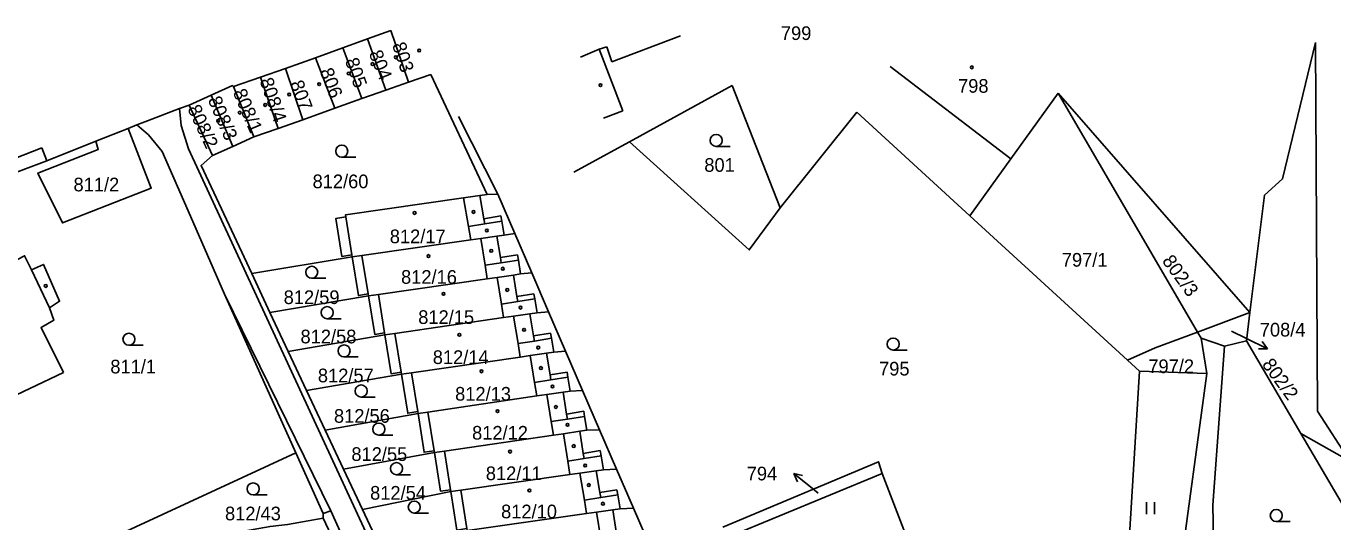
# Model space of a CAD drawing. Extents: x -776701 to -776081, y -974398 to -973771.
# Drawn here: x -776392 to -776229.3, y -973832.8 to -973771.1 of the extents above; entities that cross this region are included whole.
import ezdxf

# ---------------------------------------------------------------- set-up
doc = ezdxf.new("R2010")
doc.units = 0
for name, color, linetype in [('Hranice parcel', 7, 'Continuous'), ('Parcelní čísla', 7, 'Continuous'), ('Pop  PČ popisy', 7, 'Continuous'), ('Vnitřní kresba', 7, 'Continuous'), ('Značky budov', 7, 'Continuous'), ('Značky kultur', 7, 'Continuous')]:
    doc.layers.add(name, color=color, linetype=linetype)

msp = doc.modelspace()

# ---------------------------------------------------------------- linework, layer by layer
at = {"layer": 'Hranice parcel'}
for p, q in [((-776349.48, -973772.73), (-776352.55, -973773.84)), ((-776346.57, -973771.67), (-776349.48, -973772.73)), ((-776349.48, -973772.73), (-776347.21, -973779.11)), ((-776346.57, -973771.67), (-776344.4, -973778.13)), ((-776352.55, -973773.84), (-776355.96, -973775.07)), ((-776352.55, -973773.84), (-776350.2, -973780.16)), ((-776231.52, -973773.2), (-776231.27, -973819.06)), ((-776355.96, -973775.07), (-776359.71, -973776.43)), ((-776355.96, -973775.07), (-776353.54, -973781.33)), ((-776362.79, -973777.49), (-776366.18, -973778.65)), ((-776359.71, -973776.43), (-776362.79, -973777.49)), ((-776360.61, -973783.88), (-776362.79, -973777.49)), ((-776359.71, -973776.43), (-776357.53, -973782.82)), ((-776344.4, -973778.13), (-776341.61, -973777.15)), ((-776334.61, -973792.1), (-776341.61, -973777.15)), ((-776366.18, -973778.65), (-776363.61, -973784.92)), ((-776350.2, -973780.16), (-776347.21, -973779.11)), ((-776347.21, -973779.11), (-776344.4, -973778.13)), ((-776316.87, -973785.52), (-776304.09, -973778.55)), ((-776304.09, -973778.55), (-776298.13, -973793.76)), ((-776246.18, -973809.21), (-776263.55, -973779.48)), ((-776263.55, -973779.48), (-776239.66, -973806.76)), ((-776371.66, -973780.97), (-776372.87, -973781.39)), ((-776368.93, -973779.73), (-776371.66, -973780.97)), ((-776371.66, -973780.97), (-776368.77, -973787.24)), ((-776366.25, -973786.11), (-776368.93, -973779.73)), ((-776353.54, -973781.33), (-776350.2, -973780.16)), ((-776360.61, -973783.88), (-776357.53, -973782.82)), ((-776357.53, -973782.82), (-776353.54, -973781.33)), ((-776288.6, -973781.83), (-776298.13, -973793.76)), ((-776274.51, -973794.74), (-776288.6, -973781.83)), ((-776379.29, -973783.88), (-776383.3, -973785.47)), ((-776378.19, -973783.44), (-776379.29, -973783.88)), ((-776363.61, -973784.92), (-776360.61, -973783.88)), ((-776366.25, -973786.11), (-776363.61, -973784.92)), ((-776368.77, -973787.24), (-776366.25, -973786.11)), ((-776237.86, -973792.19), (-776239.66, -973806.76)), ((-776254.9, -973812.71), (-776274.51, -973794.74)), ((-776329.05, -973801.83), (-776331.17, -973796.94)), ((-776351.39, -973799.85), (-776363.9, -973801.91)), ((-776361.62, -973806.76), (-776363.9, -973801.91)), ((-776326.94, -973806.71), (-776329.05, -973801.83)), ((-776349.35, -973804.71), (-776361.62, -973806.76)), ((-776359.35, -973811.61), (-776361.62, -973806.76)), ((-776324.83, -973811.6), (-776326.94, -973806.71)), ((-776239.66, -973806.76), (-776246.18, -973809.21)), ((-776239.66, -973806.76), (-776240.1, -973810.31)), ((-776347.32, -973809.55), (-776359.35, -973811.61)), ((-776245.75, -973809.95), (-776246.18, -973809.21)), ((-776242.84, -973810.95), (-776245.75, -973809.95)), ((-776245.75, -973809.95), (-776245.02, -973814.37)), ((-776240.1, -973810.31), (-776242.84, -973810.95)), ((-776233.34, -973821.83), (-776240.1, -973810.31)), ((-776357.07, -973816.46), (-776359.35, -973811.61)), ((-776322.72, -973816.48), (-776324.83, -973811.6)), ((-776253.42, -973814.06), (-776254.9, -973812.71)), ((-776345.26, -973814.46), (-776357.07, -973816.46)), ((-776255.89, -973854.42), (-776253.42, -973814.06)), ((-776245.02, -973814.37), (-776253.42, -973814.06)), ((-776354.75, -973821.4), (-776357.07, -973816.46)), ((-776320.6, -973821.36), (-776322.72, -973816.48)), ((-776343.2, -973819.35), (-776354.75, -973821.4)), ((-776352.47, -973826.25), (-776354.75, -973821.4)), ((-776318.49, -973826.25), (-776320.6, -973821.36)), ((-776220.95, -973842.92), (-776233.34, -973821.83)), ((-776358.4, -973824.22), (-776389.33, -973838.52)), ((-776341.16, -973824.21), (-776352.47, -973826.25)), ((-776350.11, -973831.28), (-776352.47, -973826.25)), ((-776316.38, -973831.13), (-776318.49, -973826.25)), ((-776285.43, -973826.82), (-776304.74, -973834.76)), ((-776278.45, -973844.96), (-776285.43, -973826.82)), ((-776339.12, -973829.06), (-776350.11, -973831.28)), ((-776347.94, -973835.9), (-776350.11, -973831.28)), ((-776314.27, -973836.02), (-776316.38, -973831.13)), ((-776352.67, -973837.34), (-776354.99, -973832.34))]:
    msp.add_line(p, q, dxfattribs=at)
for points in [[(-776237.86, -973792.19), (-776235.61, -973790.15), (-776231.52, -973773.2)], [(-776366.18, -973778.65), (-776366.29, -973778.54), (-776368.93, -973779.73)], [(-776274.51, -973794.74), (-776269.43, -973787.66), (-776263.55, -973779.48)], [(-776372.87, -973781.39), (-776376.87, -973782.92), (-776378.19, -973783.44)], [(-776372.87, -973781.39), (-776372.69, -973783.49), (-776371.76, -973786.4), (-776344.07, -973846.28), (-776320.78, -973896.42)], [(-776379.29, -973783.88), (-776376.4, -973791.29), (-776387.45, -973795.62), (-776390.5, -973789.42), (-776383, -973786.49), (-776383.3, -973785.47)], [(-776378.19, -973783.44), (-776376.74, -973784.67), (-776375.05, -973786.75), (-776371.5, -973794.8), (-776367.29, -973804.51), (-776358.4, -973824.22)], [(-776383.3, -973785.47), (-776389.4, -973787.9), (-776406.97, -973794.51)], [(-776298.13, -973793.76), (-776301.98, -973798.98), (-776316.87, -973785.52)], [(-776363.9, -973801.91), (-776370.19, -973788.49), (-776368.77, -973787.24)], [(-776334.61, -973792.1), (-776335.5, -973792.23), (-776337.53, -973792.52), (-776352.21, -973794.62), (-776352.17, -973794.87), (-776353.42, -973795.06), (-776352.68, -973799.8), (-776351.43, -973799.6), (-776351.39, -973799.85)], [(-776331.17, -973796.94), (-776333.28, -973792.06), (-776334.61, -973792.1)], [(-776387.3, -973814.25), (-776390.1, -973808.63), (-776388.5, -973807.73), (-776389.05, -973806.2), (-776387.8, -973805.38), (-776389.82, -973800.79), (-776391.31, -973801.47), (-776392.16, -973799.72), (-776393.84, -973800.61), (-776396.57, -973794.81), (-776405.01, -973798.86), (-776395.74, -973818.2), (-776387.3, -973814.25)], [(-776331.17, -973796.94), (-776332.48, -973797.15), (-776333.37, -973797.28), (-776335.4, -973797.57), (-776336.64, -973797.75), (-776350.2, -973799.68), (-776351.39, -973799.85)], [(-776351.39, -973799.85), (-776350.62, -973804.66), (-776349.39, -973804.46), (-776349.35, -973804.71)], [(-776329.05, -973801.83), (-776330.43, -973801.98), (-776331.32, -973802.11), (-776333.35, -973802.4), (-776334.59, -973802.58), (-776348.11, -973804.53), (-776349.35, -973804.71)], [(-776349.35, -973804.71), (-776348.59, -973809.5), (-776347.36, -973809.3), (-776347.32, -973809.55)], [(-776326.94, -973806.71), (-776328.39, -973806.81), (-776329.28, -973806.94), (-776331.31, -973807.23), (-776332.55, -973807.41), (-776346.08, -973809.37), (-776347.32, -973809.55)], [(-776347.32, -973809.55), (-776346.53, -973814.41), (-776345.3, -973814.21), (-776345.26, -973814.46)], [(-776254.9, -973812.71), (-776251.48, -973811.15), (-776246.18, -973809.21)], [(-776324.83, -973811.6), (-776326.31, -973811.71), (-776327.2, -973811.84), (-776329.23, -973812.13), (-776330.47, -973812.31), (-776344.02, -973814.28), (-776345.26, -973814.46)], [(-776242.84, -973810.95), (-776244.28, -973830.76), (-776244.11, -973839.24), (-776247.09, -973857.16), (-776245.46, -973861.6)], [(-776345.26, -973814.46), (-776344.48, -973819.31), (-776343.24, -973819.11), (-776343.2, -973819.35)], [(-776245.02, -973814.37), (-776248.48, -973839.74), (-776251.52, -973854.49), (-776250.03, -973856.15)], [(-776322.72, -973816.48), (-776324.26, -973816.55), (-776325.15, -973816.68), (-776327.18, -973816.98), (-776328.42, -973817.16), (-776341.96, -973819.17), (-776343.2, -973819.35)], [(-776343.2, -973819.35), (-776342.44, -973824.16), (-776341.2, -973823.97), (-776341.16, -973824.21)], [(-776231.27, -973819.06), (-776227.23, -973825.26), (-776233.34, -973821.83)], [(-776320.6, -973821.36), (-776322.19, -973821.42), (-776323.08, -973821.55), (-776325.11, -973821.85), (-776326.35, -973822.03), (-776339.92, -973824.03), (-776341.16, -973824.21)], [(-776354.99, -973832.34), (-776354.99, -973831.79), (-776358.4, -973824.22)], [(-776341.16, -973824.21), (-776340.4, -973829.01), (-776339.16, -973828.82), (-776339.12, -973829.06)], [(-776318.49, -973826.25), (-776320.13, -973826.33), (-776321.02, -973826.46), (-776323.05, -973826.75), (-776324.29, -973826.93), (-776337.88, -973828.88), (-776339.12, -973829.06)], [(-776285.43, -973826.82), (-776285.89, -973825.34), (-776305.26, -973833.49)], [(-776339.12, -973829.06), (-776338.37, -973833.84), (-776337.14, -973833.65), (-776337.1, -973833.89)], [(-776316.38, -973831.13), (-776318.06, -973831.21), (-776318.95, -973831.33), (-776320.98, -973831.62), (-776322.22, -973831.79), (-776335.86, -973833.72), (-776337.1, -973833.89)], [(-776354.99, -973832.34), (-776359.44, -973833.16), (-776361.61, -973833.38), (-776376.11, -973835.95), (-776375.11, -973841.2)]]:
    msp.add_lwpolyline(points, dxfattribs=at)
at = {"layer": 'Pop  PČ popisy'}
for p, q in [((-776241.96, -973809.1), (-776240.17, -973809.97)), ((-776240.17, -973809.97), (-776237.47, -973811.29)), ((-776237.47, -973811.29), (-776238.15, -973810.4)), ((-776237.47, -973811.29), (-776238.59, -973811.3)), ((-776294.11, -973828.69), (-776296.44, -973826.8)), ((-776296.44, -973826.8), (-776295.35, -973827.04)), ((-776296.44, -973826.8), (-776295.98, -973827.82)), ((-776293.39, -973829.27), (-776294.11, -973828.69))]:
    msp.add_line(p, q, dxfattribs=at)
at = {"layer": 'Vnitřní kresba'}
for p, q in [((-776310.53, -973772.37), (-776319.09, -973775.6)), ((-776320.64, -973774), (-776322.96, -973775)), ((-776319.7, -973773.7), (-776320.64, -973774)), ((-776320.64, -973774), (-776317.69, -973781.7)), ((-776319.09, -973775.6), (-776319.7, -973773.7)), ((-776269.43, -973787.66), (-776284.44, -973776.16)), ((-776333.28, -973792.06), (-776338.14, -973782.38)), ((-776317.69, -973781.7), (-776320.11, -973782.59)), ((-776316.87, -973785.52), (-776323.79, -973789.3)), ((-776390.01, -973786.27), (-776408.2, -973793.39)), ((-776389.4, -973787.9), (-776390.01, -973786.27)), ((-776337.53, -973792.52), (-776336.92, -973796.08)), ((-776335.01, -973795.11), (-776335.5, -973792.23)), ((-776351.43, -973799.6), (-776352.17, -973794.87)), ((-776336.92, -973796.08), (-776334.9, -973795.75)), ((-776332.89, -973794.75), (-776335.01, -973795.11)), ((-776335.01, -973795.11), (-776334.9, -973795.75)), ((-776334.9, -973795.75), (-776332.78, -973795.39)), ((-776332.78, -973795.39), (-776332.89, -973794.75)), ((-776332.78, -973795.39), (-776332.48, -973797.15)), ((-776336.92, -973796.08), (-776336.64, -973797.75)), ((-776332.94, -973799.95), (-776333.37, -973797.28)), ((-776335.4, -973797.57), (-776334.86, -973800.9)), ((-776350.2, -973799.68), (-776349.39, -973804.46)), ((-776334.86, -973800.9), (-776332.83, -973800.59)), ((-776332.94, -973799.95), (-776330.81, -973799.61)), ((-776332.83, -973800.59), (-776332.94, -973799.95)), ((-776330.71, -973800.25), (-776332.83, -973800.59)), ((-776330.81, -973799.61), (-776330.71, -973800.25)), ((-776330.71, -973800.25), (-776330.43, -973801.98)), ((-776389.05, -973806.2), (-776391.31, -973801.47)), ((-776334.86, -973800.9), (-776334.59, -973802.58)), ((-776331.32, -973802.11), (-776330.89, -973804.78)), ((-776332.82, -973805.73), (-776333.35, -973802.4)), ((-776367.29, -973804.51), (-776354.06, -973831.46)), ((-776348.11, -973804.53), (-776347.36, -973809.3)), ((-776330.79, -973805.42), (-776332.82, -973805.73)), ((-776328.77, -973804.44), (-776330.89, -973804.78)), ((-776330.89, -973804.78), (-776330.79, -973805.42)), ((-776330.79, -973805.42), (-776328.66, -973805.08)), ((-776328.66, -973805.08), (-776328.77, -973804.44)), ((-776328.39, -973806.81), (-776328.66, -973805.08)), ((-776332.55, -973807.41), (-776332.82, -973805.73)), ((-776329.28, -973806.94), (-776328.83, -973809.68)), ((-776330.75, -973810.63), (-776331.31, -973807.23)), ((-776346.08, -973809.37), (-776345.3, -973814.21)), ((-776328.72, -973810.32), (-776330.75, -973810.63)), ((-776326.71, -973809.33), (-776328.83, -973809.68)), ((-776328.83, -973809.68), (-776328.72, -973810.32)), ((-776328.72, -973810.32), (-776326.6, -973809.97)), ((-776326.6, -973809.97), (-776326.71, -973809.33)), ((-776326.31, -973811.71), (-776326.6, -973809.97)), ((-776330.47, -973812.31), (-776330.75, -973810.63)), ((-776327.2, -973811.84), (-776326.76, -973814.53)), ((-776328.69, -973815.48), (-776329.23, -973812.13)), ((-776344.02, -973814.28), (-776343.24, -973819.11)), ((-776326.66, -973815.17), (-776328.69, -973815.48)), ((-776324.64, -973814.19), (-776326.76, -973814.53)), ((-776326.76, -973814.53), (-776326.66, -973815.17)), ((-776326.66, -973815.17), (-776324.54, -973814.83)), ((-776324.54, -973814.83), (-776324.64, -973814.19)), ((-776324.26, -973816.55), (-776324.54, -973814.83)), ((-776328.42, -973817.16), (-776328.69, -973815.48)), ((-776326.63, -973820.35), (-776327.18, -973816.98)), ((-776325.15, -973816.68), (-776324.7, -973819.41)), ((-776341.96, -973819.17), (-776341.2, -973823.97)), ((-776324.6, -973820.05), (-776326.63, -973820.35)), ((-776324.7, -973819.41), (-776322.58, -973819.06)), ((-776324.6, -973820.05), (-776324.7, -973819.41)), ((-776322.48, -973819.7), (-776324.6, -973820.05)), ((-776322.58, -973819.06), (-776322.48, -973819.7)), ((-776322.19, -973821.42), (-776322.48, -973819.7)), ((-776326.35, -973822.03), (-776326.63, -973820.35)), ((-776324.56, -973825.25), (-776325.11, -973821.85)), ((-776322.64, -973824.3), (-776323.08, -973821.55)), ((-776339.92, -973824.03), (-776339.16, -973828.82)), ((-776322.53, -973824.94), (-776324.56, -973825.25)), ((-776320.51, -973823.95), (-776322.64, -973824.3)), ((-776322.64, -973824.3), (-776322.53, -973824.94)), ((-776322.53, -973824.94), (-776320.41, -973824.59)), ((-776320.41, -973824.59), (-776320.51, -973823.95)), ((-776320.13, -973826.33), (-776320.41, -973824.59)), ((-776324.29, -973826.93), (-776324.56, -973825.25)), ((-776321.02, -973826.46), (-776320.57, -973829.17)), ((-776322.5, -973830.11), (-776323.05, -973826.75)), ((-776337.88, -973828.88), (-776337.14, -973833.65)), ((-776320.46, -973829.81), (-776322.5, -973830.11)), ((-776318.45, -973828.82), (-776320.57, -973829.17)), ((-776320.57, -973829.17), (-776320.46, -973829.81)), ((-776320.46, -973829.81), (-776318.34, -973829.46)), ((-776318.34, -973829.46), (-776318.45, -973828.82)), ((-776318.06, -973831.21), (-776318.34, -973829.46)), ((-776354.06, -973831.46), (-776354.99, -973831.79)), ((-776354.06, -973831.46), (-776346.76, -973847.6)), ((-776322.22, -973831.79), (-776322.5, -973830.11)), ((-776318.52, -973834), (-776318.95, -973831.33)), ((-776320.45, -973834.94), (-776320.98, -973831.62))]:
    msp.add_line(p, q, dxfattribs=at)
at = {"layer": 'Značky budov'}
for centre in [(-776343.05, -973774.18), (-776348.85, -973775.86), (-776345.97, -973775.02), (-776274.27, -973776.27), (-776351.82, -973777.03), (-776359.23, -973779.64), (-776355.5, -973778.36), (-776320.49, -973778.48), (-776362.21, -973780.95), (-776368.08, -973782.93), (-776365.39, -973781.91), (-776343.62, -973794.39), (-776336.29, -973794.26), (-776334.63, -973796.57), (-776334.08, -973799.11), (-776341.9, -973799.75), (-776332.65, -973801.32), (-776389.53, -973803.47), (-776332.09, -973803.97), (-776340.02, -973804.46), (-776330.44, -973806.17), (-776330, -973808.93), (-776338.05, -973809.54), (-776328.23, -973811.14), (-776327.9, -973813.68), (-776335.3, -973814.09), (-776326.47, -973815.99), (-776326.03, -973818.53), (-776333.3, -973819.04), (-776324.59, -973820.74), (-776323.82, -973823.39), (-776331.75, -973824.08), (-776322.39, -973825.81), (-776321.95, -973828.24), (-776329.34, -973828.93), (-776320.18, -973830.56)]:
    msp.add_circle(centre, 0.175, dxfattribs=at)
at = {"layer": 'Značky kultur'}
for p, q in [((-776352.69, -973787.45), (-776350.94, -973787.45)), ((-776306.09, -973786.11), (-776304.34, -973786.11)), ((-776356.43, -973802.52), (-776354.68, -973802.52)), ((-776354.51, -973807.54), (-776352.76, -973807.54)), ((-776379.17, -973810.85), (-776377.42, -973810.85)), ((-776284.07, -973811.45), (-776282.32, -973811.45)), ((-776352.4, -973812.3), (-776350.65, -973812.3)), ((-776350.27, -973817.29), (-776348.52, -973817.29)), ((-776348.07, -973822.03), (-776346.32, -973822.03)), ((-776345.88, -973826.95), (-776344.13, -973826.95)), ((-776363.71, -973829.47), (-776361.96, -973829.47)), ((-776252.56, -973831.86), (-776252.56, -973830.36)), ((-776251.56, -973831.86), (-776251.56, -973830.36)), ((-776343.66, -973831.73), (-776341.91, -973831.73)), ((-776236.39, -973832.78), (-776234.64, -973832.78))]:
    msp.add_line(p, q, dxfattribs=at)
for centre in [(-776352.69, -973786.7), (-776306.09, -973785.36), (-776356.43, -973801.77), (-776354.51, -973806.79), (-776379.17, -973810.1), (-776284.07, -973810.7), (-776352.4, -973811.55), (-776350.27, -973816.54), (-776348.07, -973821.28), (-776345.88, -973826.2), (-776363.71, -973828.72), (-776343.66, -973830.98), (-776236.39, -973832.03)]:
    msp.add_circle(centre, 0.75, dxfattribs=at)

# ---------------------------------------------------------------- texts
at = {"layer": 'Parcelní čísla'}
for s, p in [('799', (-776298.04, -973772.87)), ('798', (-776275.99, -973779.43)), ('801', (-776307.57, -973789.27)), ('811/2', (-776386.07, -973791.7)), ('812/60', (-776356.32, -973791.31)), ('812/17', (-776346.71, -973798.15)), ('797/1', (-776263.08, -973801.07)), ('812/16', (-776345.31, -973803.2)), ('812/59', (-776359.92, -973805.72)), ('812/15', (-776343.17, -973808.2)), ('812/58', (-776357.82, -973810.61)), ('708/4', (-776238.44, -973809.76)), ('812/14', (-776341.36, -973813.18)), ('811/1', (-776381.49, -973814.35)), ('812/57', (-776355.66, -973815.46)), ('795', (-776285.82, -973814.61)), ('797/2', (-776252.31, -973814.31)), ('812/13', (-776338.58, -973817.74)), ('812/56', (-776353.66, -973820.49)), ('812/12', (-776336.47, -973822.59)), ('812/55', (-776351.49, -973825.24)), ('812/11', (-776334.76, -973827.63)), ('794', (-776302.29, -973827.66)), ('812/54', (-776349.16, -973830.06)), ('812/43', (-776367.22, -973832.63)), ('812/10', (-776332.86, -973832.38))]:
    msp.add_text(s, height=1.7, dxfattribs=at).set_placement(p)
for s, rotation, p in [('804', 292, (-776349.35, -973774.53)), ('803', 288, (-776346.44, -973773.45)), ('805', 289, (-776352.31, -973775.41)), ('808/4', 289, (-776362.94, -973777.89)), ('807', 290, (-776359.16, -973778.24)), ('806', 291, (-776355.46, -973776.73)), ('808/1', 293, (-776366.27, -973779.36)), ('808/2', 295, (-776371.93, -973781.4)), ('808/3', 293, (-776369.38, -973780.29)), ('802/3', 306, (-776250.67, -973800.37)), ('802/2', 306, (-776238.24, -973813.24))]:
    msp.add_text(s, height=1.7, rotation=rotation, dxfattribs=at).set_placement(p)

doc.saveas('drawing.dxf')
